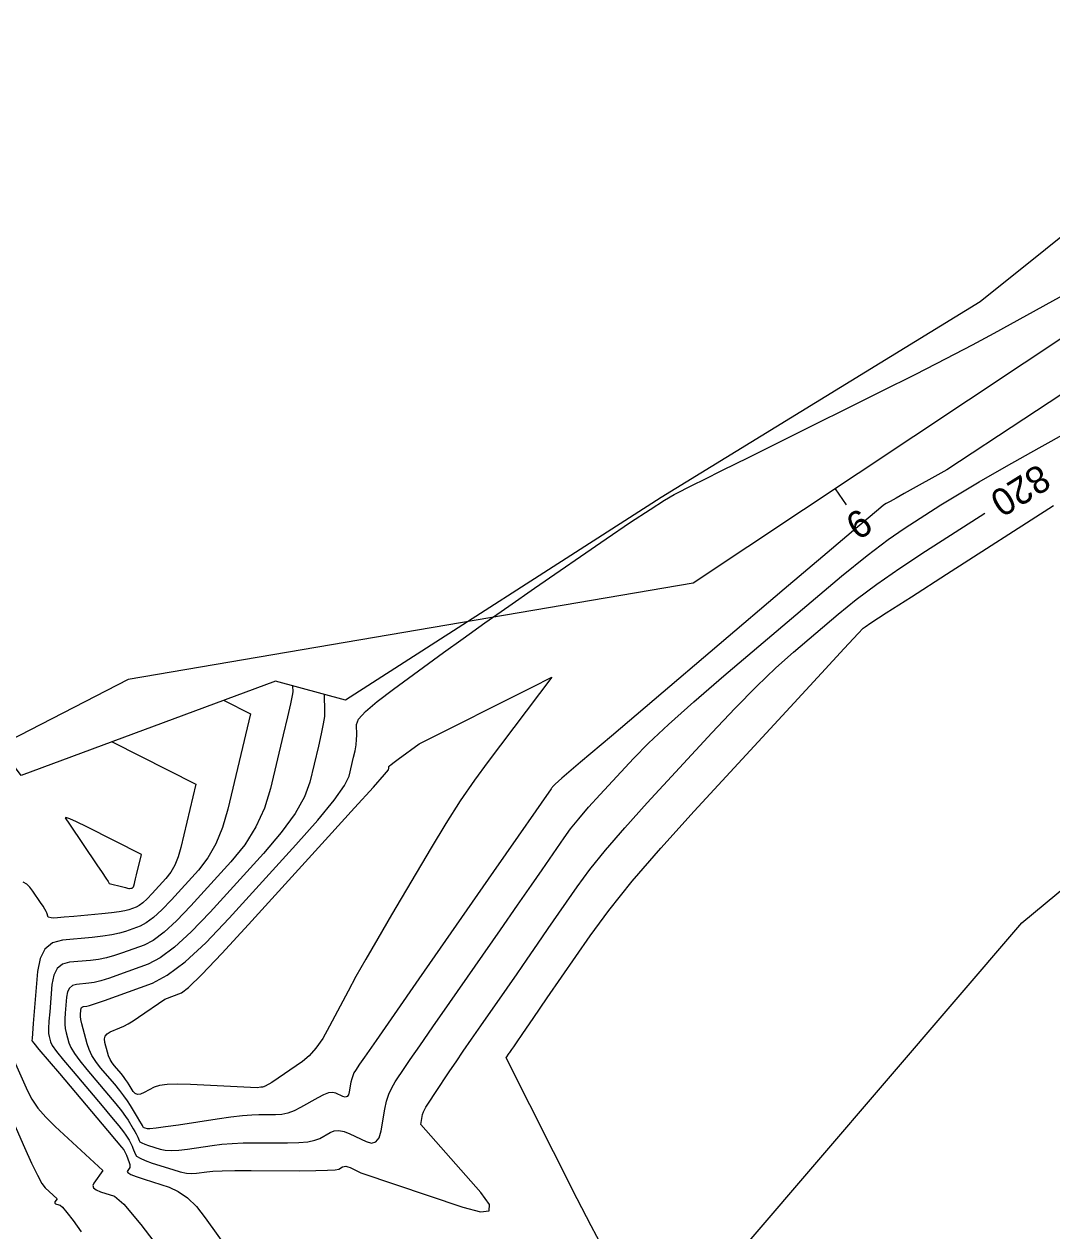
# Model space of a CAD drawing. Extents: x 1715724 to 1716561, y 394063 to 395906.
# Drawn here: x 1716106.1 to 1716159.2, y 395059.6 to 395121.9 of the extents above; entities that cross this region are included whole.
import ezdxf

# ---------------------------------------------------------------- set-up
doc = ezdxf.new("R2010")
doc.units = 0
for name, color, linetype in [('DT_X_Contour_Major', 7, 'Continuous'), ('DT_X_Contour_Minor', 7, 'Continuous'), ('DT_X_TIN_Hull', 7, 'Continuous'), ('GE_P_CL_10', 7, 'Continuous')]:
    doc.layers.add(name, color=color, linetype=linetype)

msp = doc.modelspace()

# ---------------------------------------------------------------- linework, layer by layer
at = {"layer": 'DT_X_Contour_Major'}
msp.add_lwpolyline([(1716119.997, 395087.716), (1716120.006, 395087.407), (1716119.977, 395087.22), (1716119.886, 395086.789), (1716119.733, 395086.116), (1716119.518, 395085.199), (1716118.861, 395082.431), (1716118.549, 395081.416), (1716118.103, 395080.447), (1716117.525, 395079.523), (1716116.814, 395078.644), (1716114.74, 395076.363), (1716114.007, 395075.596), (1716113.364, 395075.004), (1716112.809, 395074.587), (1716112.344, 395074.346), (1716111.223, 395073.938), (1716110.804, 395073.799), (1716110.388, 395073.689), (1716109.976, 395073.608), (1716109.568, 395073.556), (1716108.482, 395073.456), (1716108.121, 395073.356), (1716107.85, 395073.133), (1716107.669, 395072.786), (1716107.58, 395072.315), (1716107.461, 395070.895), (1716107.426, 395070.416), (1716107.409, 395070.044), (1716107.409, 395069.779), (1716107.428, 395069.621), (1716107.501, 395069.343), (1716107.595, 395069.169), (1716107.822, 395068.856), (1716108.182, 395068.405), (1716108.674, 395067.814), (1716110.164, 395066.055), (1716110.66, 395065.465), (1716111.032, 395065.016), (1716111.278, 395064.707), (1716111.4, 395064.538), (1716111.557, 395064.274), (1716111.614, 395064.173), (1716111.666, 395064.071), (1716111.714, 395063.965), (1716111.757, 395063.857), (1716111.865, 395063.566), (1716111.95, 395063.455), (1716112.126, 395063.339), (1716112.392, 395063.219), (1716112.748, 395063.095), (1716113.817, 395062.757), (1716114.194, 395062.65), (1716114.522, 395062.582), (1716114.801, 395062.554), (1716115.031, 395062.565), (1716115.58, 395062.646), (1716115.878, 395062.673), (1716116.358, 395062.692), (1716117.02, 395062.703), (1716117.866, 395062.706), (1716120.364, 395062.702), (1716121.192, 395062.707), (1716121.805, 395062.722), (1716122.201, 395062.747), (1716122.382, 395062.783), (1716122.575, 395062.894), (1716122.653, 395062.923), (1716122.744, 395062.927), (1716122.847, 395062.906), (1716122.962, 395062.86), (1716123.528, 395062.587), (1716128.791, 395060.823), (1716129.695, 395060.586), (1716130.151, 395060.632), (1716130.159, 395060.962), (1716129.718, 395061.574), (1716126.619, 395065.092), (1716126.707, 395065.597), (1716126.761, 395065.746), (1716126.883, 395065.978), (1716127.073, 395066.29), (1716127.333, 395066.685), (1716128.116, 395067.847), (1716128.436, 395068.319), (1716128.81, 395068.864), (1716129.236, 395069.483), (1716129.716, 395070.174), (1716131.067, 395072.115), (1716131.58, 395072.853), (1716132.106, 395073.612), (1716132.645, 395074.392), (1716133.197, 395075.193), (1716134.687, 395077.357), (1716135.332, 395078.236), (1716136.149, 395079.25), (1716137.139, 395080.4), (1716138.302, 395081.685), (1716141.632, 395085.293), (1716142.832, 395086.569), (1716143.937, 395087.689), (1716144.944, 395088.655), (1716145.856, 395089.465), (1716148.158, 395091.42), (1716149.086, 395092.172), (1716150.147, 395092.964), (1716151.339, 395093.796), (1716152.662, 395094.666), (1716155.728, 395096.632)], dxfattribs=at)
at = {"layer": 'DT_X_Contour_Minor'}
for points in [[(1716110.093, 395068.016), (1716109.844, 395068.335), (1716109.645, 395068.645), (1716109.495, 395068.948), (1716109.394, 395069.243), (1716109.189, 395070.019), (1716109.122, 395070.285), (1716109.077, 395070.498), (1716109.052, 395070.66), (1716109.049, 395070.769), (1716109.068, 395070.993), (1716109.082, 395071.067), (1716109.11, 395071.122), (1716109.153, 395071.157), (1716109.21, 395071.173), (1716109.381, 395071.189), (1716109.524, 395071.226), (1716109.825, 395071.324), (1716110.285, 395071.485), (1716110.903, 395071.708), (1716112.761, 395072.385), (1716113.532, 395072.784), (1716114.451, 395073.475), (1716115.518, 395074.456), (1716116.732, 395075.728), (1716120.169, 395079.509), (1716121.307, 395080.795), (1716122.145, 395081.816), (1716122.682, 395082.574), (1716122.918, 395083.068), (1716123.147, 395084.034), (1716123.221, 395084.376), (1716123.273, 395084.68), (1716123.301, 395084.946), (1716123.306, 395085.173), (1716123.288, 395085.727), (1716123.404, 395085.997), (1716123.762, 395086.391), (1716124.363, 395086.91), (1716125.208, 395087.553), (1716127.784, 395089.435), (1716128.803, 395090.171), (1716129.926, 395090.97), (1716131.154, 395091.832), (1716132.487, 395092.756), (1716136.182, 395095.303), (1716137.441, 395096.162), (1716138.445, 395096.83), (1716139.196, 395097.305), (1716139.692, 395097.589), (1716140.678, 395098.091), (1716141.241, 395098.374), (1716142.191, 395098.848), (1716143.526, 395099.513), (1716145.249, 395100.369), (1716150.357, 395102.905), (1716152.159, 395103.806), (1716153.735, 395104.609), (1716155.085, 395105.313), (1716156.208, 395105.918), (1716160.921, 395108.512)], [(1716161.706, 395104.096), (1716153.757, 395098.866), (1716151.558, 395097.642), (1716151.142, 395097.41), (1716150.836, 395097.238), (1716150.641, 395097.128), (1716150.555, 395097.078), (1716150.475, 395097.026), (1716150.133, 395096.742), (1716149.17, 395095.928), (1716147.585, 395094.584), (1716145.377, 395092.71), (1716138.661, 395087.007), (1716136.453, 395085.131), (1716134.865, 395083.779), (1716133.898, 395082.952), (1716133.55, 395082.65), (1716133.452, 395082.543), (1716133.418, 395082.505), (1716133.388, 395082.471), (1716133.364, 395082.441), (1716133.345, 395082.415), (1716133.301, 395082.351), (1716133.106, 395082.07), (1716132.553, 395081.276), (1716131.643, 395079.968), (1716130.375, 395078.145), (1716126.517, 395072.602), (1716125.241, 395070.767), (1716124.306, 395069.422), (1716123.712, 395068.567), (1716123.459, 395068.2), (1716123.241, 395067.876), (1716123.165, 395067.746), (1716123.101, 395067.601), (1716123.051, 395067.44), (1716123.012, 395067.264), (1716122.926, 395066.772), (1716122.88, 395066.619), (1716122.809, 395066.528), (1716122.712, 395066.5), (1716122.588, 395066.534), (1716122.225, 395066.709), (1716122.065, 395066.743), (1716121.856, 395066.713), (1716121.599, 395066.62), (1716121.293, 395066.463), (1716120.414, 395065.959), (1716120.086, 395065.793), (1716119.76, 395065.675), (1716119.436, 395065.605), (1716119.115, 395065.581), (1716118.262, 395065.583), (1716117.888, 395065.569), (1716117.405, 395065.527), (1716116.814, 395065.457), (1716116.114, 395065.359), (1716114.104, 395065.059), (1716113.438, 395064.963), (1716112.95, 395064.898), (1716112.639, 395064.865), (1716112.504, 395064.863), (1716112.383, 395064.902), (1716112.343, 395064.916), (1716112.313, 395064.929), (1716112.293, 395064.942), (1716112.283, 395064.955), (1716112.271, 395064.988), (1716112.25, 395065.027), (1716112.197, 395065.119), (1716112.111, 395065.265), (1716111.993, 395065.463), (1716111.634, 395066.064), (1716111.482, 395066.301), (1716111.296, 395066.562), (1716111.075, 395066.848), (1716110.82, 395067.158), (1716110.093, 395068.016)], [(1716121.625, 395087.273), (1716121.653, 395086.393), (1716121.637, 395086.141), (1716121.579, 395085.761), (1716121.477, 395085.252), (1716121.333, 395084.616), (1716120.89, 395082.75), (1716120.615, 395081.995), (1716120.124, 395081.131), (1716119.416, 395080.159), (1716118.491, 395079.077), (1716115.736, 395076.046), (1716114.762, 395075.026), (1716113.907, 395074.239), (1716113.171, 395073.686), (1716112.553, 395073.366), (1716111.063, 395072.823), (1716110.544, 395072.642), (1716110.107, 395072.507), (1716109.75, 395072.417), (1716109.474, 395072.372), (1716108.846, 395072.314), (1716108.637, 395072.257), (1716108.48, 395072.127), (1716108.376, 395071.927), (1716108.324, 395071.654), (1716108.255, 395070.832), (1716108.239, 395070.538), (1716108.243, 395070.271), (1716108.266, 395070.032), (1716108.308, 395069.82), (1716108.447, 395069.293), (1716108.545, 395069.058), (1716108.734, 395068.751), (1716109.013, 395068.37), (1716109.383, 395067.915), (1716110.492, 395066.606), (1716110.868, 395066.157), (1716111.164, 395065.789), (1716111.38, 395065.504), (1716111.517, 395065.301), (1716111.775, 395064.868), (1716111.863, 395064.719), (1716111.932, 395064.595), (1716111.982, 395064.496), (1716112.014, 395064.423), (1716112.074, 395064.261), (1716112.122, 395064.199), (1716112.219, 395064.134), (1716112.367, 395064.067), (1716112.566, 395063.998), (1716113.161, 395063.81), (1716113.416, 395063.757), (1716113.736, 395063.74), (1716114.119, 395063.758), (1716114.567, 395063.812), (1716115.847, 395064.003), (1716116.346, 395064.065), (1716116.881, 395064.109), (1716117.454, 395064.136), (1716118.064, 395064.144), (1716119.739, 395064.142), (1716120.314, 395064.156), (1716120.782, 395064.198), (1716121.144, 395064.27), (1716121.398, 395064.371), (1716121.934, 395064.678), (1716122.149, 395064.76), (1716122.392, 395064.776), (1716122.662, 395064.725), (1716122.96, 395064.608), (1716123.793, 395064.207), (1716124.075, 395064.128), (1716124.298, 395064.193), (1716124.461, 395064.4), (1716124.565, 395064.751), (1716124.763, 395065.878), (1716124.851, 395066.283), (1716124.968, 395066.651), (1716125.113, 395066.984), (1716125.287, 395067.281), (1716125.788, 395068.024), (1716126.074, 395068.443), (1716126.558, 395069.143), (1716127.239, 395070.125), (1716128.117, 395071.388), (1716130.721, 395075.13), (1716131.611, 395076.41), (1716132.33, 395077.444), (1716132.876, 395078.231), (1716133.249, 395078.772), (1716134.016, 395079.886), (1716134.348, 395080.338), (1716134.769, 395080.861), (1716135.278, 395081.453), (1716135.877, 395082.114), (1716137.591, 395083.971), (1716138.365, 395084.76), (1716139.401, 395085.734), (1716140.699, 395086.893), (1716142.259, 395088.236), (1716146.767, 395092.065), (1716148.336, 395093.378), (1716149.658, 395094.446), (1716150.736, 395095.269), (1716151.568, 395095.846), (1716153.46, 395097.059), (1716154.309, 395097.584), (1716155.436, 395098.249), (1716156.841, 395099.053), (1716158.525, 395099.998), (1716163.386, 395102.704)], [(1716135.998, 395058.761), (1716135.408, 395059.848), (1716134.688, 395061.251), (1716131.024, 395068.531), (1716131.178, 395068.758), (1716131.211, 395068.807), (1716131.245, 395068.857), (1716131.28, 395068.908), (1716131.316, 395068.96), (1716131.413, 395069.099), (1716131.549, 395069.296), (1716131.882, 395069.78), (1716132.415, 395070.553), (1716133.145, 395071.614), (1716135.358, 395074.827), (1716136.315, 395076.133), (1716137.529, 395077.64), (1716139, 395079.347), (1716140.726, 395081.256), (1716145.673, 395086.615), (1716147.3, 395088.377), (1716148.472, 395089.644), (1716149.19, 395090.417), (1716149.453, 395090.694), (1716149.548, 395090.774), (1716149.837, 395090.967), (1716150.635, 395091.483), (1716151.941, 395092.322), (1716153.755, 395093.486), (1716159.271, 395097.021)], [(1716110.305, 395069.324), (1716110.284, 395069.502), (1716110.324, 395069.651), (1716110.423, 395069.772), (1716110.583, 395069.863), (1716111.089, 395070.067), (1716111.291, 395070.159), (1716111.519, 395070.283), (1716111.771, 395070.437), (1716112.048, 395070.623), (1716113.4, 395071.561), (1716114.268, 395071.877), (1716114.624, 395072.149), (1716115.319, 395072.828), (1716116.354, 395073.916), (1716117.729, 395075.411), (1716121.846, 395079.941), (1716123.198, 395081.43), (1716124.166, 395082.501), (1716124.748, 395083.153), (1716124.946, 395083.387), (1716124.966, 395083.473), (1716124.972, 395083.511), (1716124.971, 395083.563), (1716125, 395083.596), (1716125.088, 395083.669), (1716125.234, 395083.782), (1716125.44, 395083.933), (1716126.535, 395084.733), (1716132.361, 395087.652), (1716133.378, 395088.163), (1716130.094, 395083.824), (1716129.382, 395082.848), (1716128.655, 395081.78), (1716127.912, 395080.621), (1716127.153, 395079.369), (1716125.109, 395075.91), (1716124.393, 395074.69), (1716123.78, 395073.625), (1716123.269, 395072.714), (1716122.861, 395071.959), (1716121.909, 395070.151), (1716121.553, 395069.529), (1716121.202, 395069.019), (1716120.855, 395068.62), (1716120.512, 395068.333), (1716118.921, 395067.254), (1716118.581, 395067.06), (1716118.539, 395067.038), (1716118.509, 395067.025), (1716118.491, 395067.021), (1716118.446, 395067.02), (1716118.359, 395067.009), (1716118.175, 395066.982), (1716114.73, 395067.144), (1716114.06, 395067.161), (1716113.524, 395067.144), (1716113.123, 395067.092), (1716112.858, 395067.005), (1716112.33, 395066.728), (1716112.147, 395066.653), (1716111.994, 395066.638), (1716111.87, 395066.682), (1716111.776, 395066.785), (1716111.565, 395067.138), (1716111.48, 395067.273), (1716111.382, 395067.413), (1716111.271, 395067.559), (1716111.148, 395067.709), (1716110.802, 395068.117), (1716110.682, 395068.275), (1716110.582, 395068.443), (1716110.502, 395068.621), (1716110.441, 395068.809), (1716110.305, 395069.324)], [(1716116.46, 395086.972), (1716117.823, 395086.284), (1716116.653, 395081.353), (1716116.381, 395080.41), (1716116.037, 395079.572), (1716115.622, 395078.839), (1716115.136, 395078.212), (1716113.744, 395076.681), (1716113.252, 395076.165), (1716112.82, 395075.768), (1716112.448, 395075.488), (1716112.135, 395075.327), (1716111.383, 395075.052), (1716111.063, 395074.956), (1716110.67, 395074.871), (1716110.203, 395074.799), (1716109.661, 395074.74), (1716108.119, 395074.597), (1716107.605, 395074.456), (1716107.219, 395074.138), (1716106.963, 395073.645), (1716106.836, 395072.976), (1716106.613, 395070.294), (1716106.553, 395069.526), (1716106.547, 395069.422), (1716106.555, 395069.393), (1716106.645, 395069.279), (1716106.91, 395068.962), (1716107.965, 395067.713), (1716110.453, 395064.774), (1716110.9, 395064.243), (1716111.176, 395063.909), (1716111.283, 395063.774), (1716111.34, 395063.679), (1716111.363, 395063.634), (1716111.391, 395063.573), (1716111.423, 395063.494), (1716111.563, 395063.121), (1716111.592, 395063.023), (1716111.602, 395062.938), (1716111.593, 395062.866), (1716111.564, 395062.807), (1716111.462, 395062.667), (1716111.489, 395062.602), (1716111.644, 395062.511), (1716111.929, 395062.396), (1716112.344, 395062.256), (1716113.622, 395061.849), (1716114.098, 395061.636), (1716114.568, 395061.301), (1716115.033, 395060.845), (1716115.491, 395060.268), (1716116.707, 395058.568)], [(1716110.684, 395084.836), (1716115.008, 395082.651), (1716114.233, 395079.383), (1716114.094, 395078.902), (1716113.918, 395078.474), (1716113.707, 395078.1), (1716113.458, 395077.78), (1716112.748, 395076.998), (1716112.497, 395076.735), (1716112.276, 395076.532), (1716112.086, 395076.39), (1716111.927, 395076.307), (1716111.543, 395076.167), (1716111.348, 395076.115), (1716111.053, 395076.063), (1716110.657, 395076.012), (1716110.16, 395075.961), (1716108.7, 395075.826), (1716108.217, 395075.783), (1716107.862, 395075.754), (1716107.636, 395075.741), (1716107.538, 395075.742), (1716107.378, 395075.783), (1716107.31, 395076.013), (1716107.279, 395076.083), (1716107.215, 395076.196), (1716107.117, 395076.351), (1716106.987, 395076.548), (1716106.594, 395077.13), (1716106.44, 395077.327), (1716106.274, 395077.483), (1716106.095, 395077.597)], [(1716111.718, 395077.288), (1716111.732, 395077.297), (1716111.741, 395077.305), (1716111.781, 395077.348), (1716111.791, 395077.361), (1716111.8, 395077.376), (1716111.807, 395077.394), (1716111.837, 395077.515), (1716111.86, 395077.613), (1716111.895, 395077.762), (1716111.943, 395077.963), (1716112.194, 395079.019), (1716109.377, 395080.441), (1716108.854, 395080.699), (1716108.494, 395080.864), (1716108.297, 395080.935), (1716108.262, 395080.913), (1716108.477, 395080.591), (1716109.903, 395078.48), (1716110.17, 395078.084), (1716110.362, 395077.798), (1716110.478, 395077.623), (1716110.518, 395077.559), (1716110.53, 395077.521), (1716111.238, 395077.341), (1716111.374, 395077.307), (1716111.477, 395077.284), (1716111.548, 395077.271), (1716111.586, 395077.268), (1716111.646, 395077.273), (1716111.666, 395077.276), (1716111.682, 395077.278), (1716111.695, 395077.28), (1716111.702, 395077.282), (1716111.718, 395077.288)], [(1716105.426, 395068.827), (1716106.309, 395066.823), (1716106.54, 395066.387), (1716106.856, 395065.936), (1716107.257, 395065.469), (1716107.742, 395064.989), (1716110.202, 395062.711), (1716109.734, 395062.066), (1716109.681, 395061.934), (1716109.721, 395061.815), (1716109.854, 395061.709), (1716110.082, 395061.615), (1716110.813, 395061.382), (1716111.289, 395060.976), (1716112.168, 395059.93), (1716113.451, 395058.246)], [(1716104.272, 395068.178), (1716106.157, 395063.903), (1716106.527, 395063.085), (1716106.829, 395062.467), (1716107.063, 395062.046), (1716107.23, 395061.824), (1716107.85, 395061.25), (1716107.732, 395061.088), (1716107.719, 395061.055), (1716107.729, 395061.025), (1716107.762, 395060.998), (1716107.82, 395060.974), (1716108.004, 395060.916), (1716108.124, 395060.813), (1716108.345, 395060.55), (1716108.669, 395060.126), (1716109.093, 395059.54)]]:
    msp.add_lwpolyline(points, dxfattribs=at)
at = {"layer": 'DT_X_TIN_Hull'}
for points in [[(1716335.246, 395223.509), (1716320.65, 395211.924), (1716306.732, 395206.826), (1716291.707, 395204.036), (1716278.005, 395208.188), (1716261.045, 395202.977), (1716243.981, 395193.78), (1716225.98, 395181.666), (1716214.77, 395165.024), (1716203.323, 395152.499), (1716198.083, 395146.196), (1716187.292, 395139.292), (1716176.967, 395127.466), (1716165.6, 395115.641), (1716155.482, 395107.53), (1716139.016, 395097.434), (1716122.723, 395086.974), (1716119.117, 395087.955), (1716105.991, 395083.1), (1716092.42, 395101.266), (1716090.336, 395107.35), (1716087.904, 395121.249), (1716081.11, 395137.012), (1716069.702, 395157.325)], [(1716173.813, 394948.174), (1716164.239, 394964.103), (1716158.601, 394970.074), (1716161.282, 395011.431), (1716153.509, 395030.897), (1716140.066, 395054.98), (1716157.64, 395075.485), (1716176.813, 395091.39), (1716197.289, 395109.746), (1716218.016, 395125.434), (1716237.91, 395140.502), (1716261.28, 395153.338), (1716300.311, 395170.239), (1716324.758, 395179.267), (1716349.419, 395190.186), (1716344.962, 395206.213), (1716337.659, 395219.828)]]:
    msp.add_lwpolyline(points, dxfattribs=at)
at = {"layer": 'GE_P_CL_10'}
for p, q in [((1716177.951, 395117.821), (1716140.673, 395093.017)), ((1716148.006, 395097.896), (1716148.56, 395097.064)), ((1716140.673, 395093.017), (1716111.51, 395088.045)), ((1716111.51, 395088.045), (1715997.389, 395029.305))]:
    msp.add_line(p, q, dxfattribs=at)

# ---------------------------------------------------------------- texts
at = {"layer": 'DT_X_Contour_Major'}
msp.add_text('820', height=1.4, rotation=211.92849, dxfattribs=at).set_placement((1716158.525, 395099.22))
at = {"layer": 'GE_P_CL_10'}
msp.add_text('9', height=1.4, rotation=213.63948, dxfattribs=at).set_placement((1716149.278, 395096.94))

doc.saveas('drawing.dxf')
